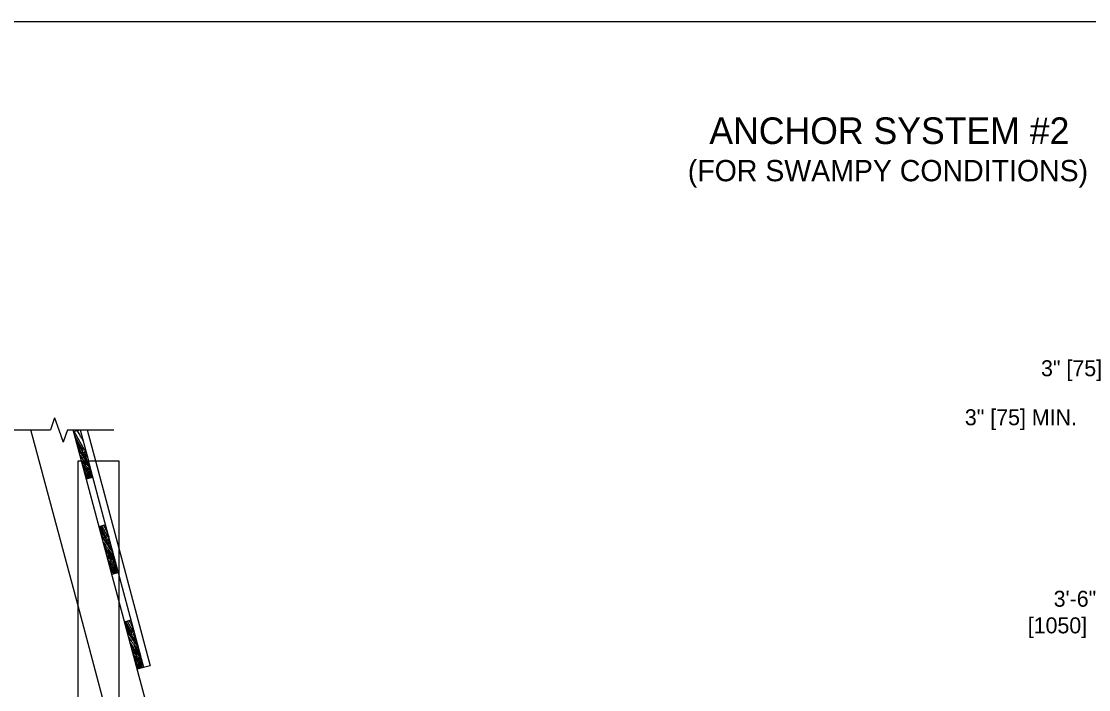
# Model space of a CAD drawing. Extents: x 49991.4 to 50021, y 49987.6 to 50011.4.
# Drawn here: x 50004.704 to 50008.713, y 49996.488 to 49998.999 of the extents above; entities that cross this region are included whole.
import ezdxf

# ---------------------------------------------------------------- set-up
doc = ezdxf.new("R2010")
doc.units = 0
for name, color, linetype in [('Level 1', 7, 'Continuous'), ('Level 2', 7, 'Continuous'), ('Level 4', 7, 'Continuous'), ('Level 6', 7, 'Continuous')]:
    doc.layers.add(name, color=color, linetype=linetype)

msp = doc.modelspace()

# ---------------------------------------------------------------- linework, layer by layer
at = {"layer": 'Level 1'}
for p, q in [((50004.9173, 49996.803), (50004.7403, 49997.464)), ((50004.9297, 49997.3481), (50004.8986, 49997.464)), ((50004.9003, 49997.4575), (50004.9249, 49997.464)), ((50004.9249, 49997.464), (50004.956, 49997.3481)), ((50004.9512, 49997.464), (50004.9825, 49997.3481)), ((50004.9173, 49995.084), (50004.9173, 49997.3481)), ((50004.9173, 49997.3481), (50004.9829, 49997.3481)), ((50004.9835, 49997.3481), (50005.0703, 49997.3481)), ((50005.0703, 49997.3481), (50005.0703, 49995.084)), ((50005.0703, 49997.0202), (50005.1888, 49996.578)), ((50005.1641, 49996.5715), (50005.0703, 49996.9218)), ((50005.2281, 49996.2339), (50005.0703, 49996.8231)), ((50005.0917, 49996.7435), (50005.1163, 49996.75)), ((50005.1887, 49996.578), (50005.1394, 49996.565))]:
    msp.add_line(p, q, dxfattribs=at)
msp.add_lwpolyline([(49999.3835, 49998.9992), (50016.7501, 49998.9992), (50016.7501, 49987.7988), (49999.3835, 49987.7988)], close=True, dxfattribs=at)
for points in [[(50004.9455, 49997.3874), (50004.9418, 49997.389), (50004.9031, 49997.4582)], [(50004.907, 49997.4327), (50004.9336, 49997.3899), (50004.9344, 49997.3884), (50004.9357, 49997.3871), (50004.9371, 49997.3841), (50004.9346, 49997.3906), (50004.933, 49997.3921), (50004.904, 49997.4439)], [(50004.9141, 49997.4611), (50004.921, 49997.4483), (50004.9236, 49997.4459), (50004.9245, 49997.4414), (50004.9271, 49997.4394), (50004.9275, 49997.4372), (50004.9283, 49997.4354), (50004.9306, 49997.4344), (50004.9362, 49997.422)], [(50004.9108, 49997.4184), (50004.9287, 49997.3903), (50004.9322, 49997.3858), (50004.9326, 49997.3821), (50004.9355, 49997.3791), (50004.9363, 49997.3743), (50004.9389, 49997.3703), (50004.941, 49997.3674), (50004.9444, 49997.3606), (50004.9482, 49997.3573), (50004.9508, 49997.3481)], [(50004.9143, 49997.4053), (50004.9236, 49997.3882), (50004.9262, 49997.3858), (50004.9271, 49997.3813), (50004.9297, 49997.3793), (50004.9301, 49997.3771), (50004.9309, 49997.3753), (50004.9332, 49997.3743), (50004.9352, 49997.3698), (50004.941, 49997.3629), (50004.9422, 49997.3595), (50004.9468, 49997.3537), (50004.9488, 49997.3481)], [(50004.9183, 49997.3905), (50004.9244, 49997.3826), (50004.9264, 49997.3785), (50004.9289, 49997.3736), (50004.9336, 49997.3685), (50004.9389, 49997.3593), (50004.9426, 49997.3544), (50004.9457, 49997.3481)], [(50004.9241, 49997.3691), (50004.9264, 49997.3679), (50004.9273, 49997.3673), (50004.9276, 49997.3657), (50004.929, 49997.3638), (50004.9308, 49997.3613), (50004.9342, 49997.3549)], [(50004.9257, 49997.3629), (50004.9284, 49997.3623), (50004.9313, 49997.3578), (50004.9349, 49997.3535), (50004.9352, 49997.3522), (50004.9365, 49997.3515)], [(50004.9531, 49997.3589), (50004.9512, 49997.3614), (50004.9482, 49997.3642), (50004.9474, 49997.3685), (50004.9434, 49997.3759), (50004.9402, 49997.3802)], [(50004.9461, 49997.3799), (50004.9451, 49997.3814), (50004.9421, 49997.385), (50004.9434, 49997.3819), (50004.9457, 49997.3799)], [(50004.9435, 49997.3757), (50004.948, 49997.3709), (50004.9509, 49997.3671)], [(50004.9395, 49997.3481), (50004.938, 49997.35), (50004.9388, 49997.3481)], [(50005.0937, 49996.7357), (50005.1118, 49996.7069), (50005.1153, 49996.7024), (50005.1157, 49996.6988), (50005.1186, 49996.6957), (50005.1194, 49996.6909), (50005.1219, 49996.6869), (50005.1241, 49996.6841), (50005.1275, 49996.6772), (50005.1313, 49996.6739), (50005.1354, 49996.6655), (50005.1371, 49996.664), (50005.1389, 49996.6591), (50005.1412, 49996.657)], [(50005.0951, 49996.7444), (50005.1167, 49996.7065), (50005.1174, 49996.705), (50005.1188, 49996.7037), (50005.1201, 49996.7007), (50005.1177, 49996.7072), (50005.1161, 49996.7087), (50005.0944, 49996.7442)], [(50005.0974, 49996.7221), (50005.1067, 49996.7048), (50005.1093, 49996.7024), (50005.1102, 49996.6979), (50005.1128, 49996.6959), (50005.1132, 49996.6937), (50005.1139, 49996.6919), (50005.1162, 49996.6909), (50005.1183, 49996.6864), (50005.1241, 49996.6795), (50005.1252, 49996.6761), (50005.1299, 49996.6703), (50005.1325, 49996.6647), (50005.1354, 49996.663), (50005.1362, 49996.6597), (50005.1394, 49996.655), (50005.143, 49996.6502)], [(50005.1286, 49996.7039), (50005.1249, 49996.7056), (50005.1022, 49996.7463)], [(50005.1084, 49996.7479), (50005.112, 49996.7413), (50005.1146, 49996.7389), (50005.1155, 49996.7344), (50005.1181, 49996.7324), (50005.1185, 49996.7302), (50005.1285, 49996.7046)], [(50005.1014, 49996.7071), (50005.1075, 49996.6992), (50005.1094, 49996.6951), (50005.112, 49996.6902), (50005.1167, 49996.6852), (50005.1219, 49996.6759), (50005.1257, 49996.671), (50005.1303, 49996.6616), (50005.1329, 49996.661), (50005.1395, 49996.6517), (50005.1424, 49996.6439), (50005.1445, 49996.6444)], [(50005.1071, 49996.6857), (50005.1095, 49996.6845), (50005.1104, 49996.6839), (50005.1106, 49996.6823), (50005.1121, 49996.6804), (50005.1139, 49996.6779), (50005.1173, 49996.6716)], [(50005.1088, 49996.6795), (50005.1115, 49996.6789), (50005.1144, 49996.6744), (50005.118, 49996.6701), (50005.1183, 49996.6688), (50005.1196, 49996.6682)], [(50005.1362, 49996.6755), (50005.1343, 49996.678), (50005.1313, 49996.6808), (50005.1305, 49996.6852), (50005.1264, 49996.6925), (50005.1233, 49996.6968)], [(50005.1292, 49996.6965), (50005.1281, 49996.698), (50005.1252, 49996.7016), (50005.1264, 49996.6985), (50005.1287, 49996.6965)], [(50005.1252, 49996.6937), (50005.1311, 49996.6875), (50005.1341, 49996.6836)], [(50005.1296, 49996.6389), (50005.1241, 49996.6487), (50005.1199, 49996.6569), (50005.1161, 49996.6625), (50005.1119, 49996.6676)], [(50005.1134, 49996.6619), (50005.1181, 49996.6535), (50005.1223, 49996.6483), (50005.118, 49996.6558), (50005.1131, 49996.6633)], [(50005.1159, 49996.6528), (50005.1228, 49996.6455), (50005.1268, 49996.6389)], [(50005.1615, 49996.5816), (50005.1535, 49996.5962), (50005.1515, 49996.5983), (50005.1479, 49996.6009), (50005.1447, 49996.6074), (50005.1378, 49996.6134), (50005.1346, 49996.6207), (50005.1279, 49996.6307), (50005.1246, 49996.6321), (50005.1226, 49996.6356), (50005.1191, 49996.6409)], [(50005.1251, 49996.6615), (50005.1241, 49996.6631), (50005.1211, 49996.6666), (50005.1224, 49996.6637), (50005.1246, 49996.6615)], [(50005.1358, 49996.6389), (50005.1315, 49996.6469), (50005.1289, 49996.6513), (50005.1276, 49996.6563), (50005.1264, 49996.6584), (50005.1293, 49996.6541), (50005.1342, 49996.6483), (50005.1379, 49996.6422), (50005.1399, 49996.6389)], [(50005.156, 49996.6019), (50005.1506, 49996.6071), (50005.1474, 49996.6138), (50005.1383, 49996.6218), (50005.1265, 49996.6388)], [(50005.1292, 49996.6388), (50005.1354, 49996.6307), (50005.1396, 49996.6238), (50005.1428, 49996.6224), (50005.1439, 49996.6207)], [(50005.1375, 49996.6389), (50005.1326, 49996.6482), (50005.1301, 49996.6512), (50005.1297, 49996.6518)], [(50005.1522, 49996.6161), (50005.1432, 49996.6274), (50005.1375, 49996.6325), (50005.1375, 49996.6363), (50005.1355, 49996.6388)], [(50005.1372, 49996.6388), (50005.1402, 49996.6349), (50005.1402, 49996.6336), (50005.1416, 49996.6311), (50005.1432, 49996.6307), (50005.1465, 49996.6259), (50005.1502, 49996.6205)], [(50005.1395, 49996.6388), (50005.1426, 49996.6332), (50005.1451, 49996.6308), (50005.1502, 49996.6233)], [(50005.155, 49996.5691), (50005.1506, 49996.5758), (50005.1468, 49996.5821), (50005.1445, 49996.5882), (50005.1439, 49996.5873), (50005.1416, 49996.5938), (50005.1387, 49996.5962), (50005.1371, 49996.6007), (50005.134, 49996.6046), (50005.131, 49996.6074), (50005.1303, 49996.6116), (50005.1239, 49996.6231)], [(50005.1245, 49996.6208), (50005.1309, 49996.614), (50005.134, 49996.6099), (50005.1375, 49996.6059), (50005.1414, 49996.6), (50005.147, 49996.5963), (50005.1507, 49996.5905), (50005.1551, 49996.5851), (50005.1632, 49996.5749)], [(50005.1289, 49996.6229), (50005.1279, 49996.6245), (50005.1249, 49996.628), (50005.1262, 49996.6251), (50005.1285, 49996.6229)], [(50005.1286, 49996.6054), (50005.1351, 49996.5921), (50005.1369, 49996.5905), (50005.1387, 49996.5856), (50005.1439, 49996.5809), (50005.1473, 49996.5726), (50005.1504, 49996.5705), (50005.1519, 49996.5683)], [(50005.1325, 49996.5911), (50005.1351, 49996.5894), (50005.136, 49996.5862), (50005.139, 49996.5815), (50005.1428, 49996.5767), (50005.1426, 49996.575), (50005.1441, 49996.5729), (50005.1484, 49996.5673)], [(50005.1338, 49996.5858), (50005.1393, 49996.5782), (50005.1422, 49996.5705), (50005.1441, 49996.5709), (50005.1473, 49996.5671)], [(50005.1574, 49996.5718), (50005.1539, 49996.5767), (50005.1502, 49996.5827), (50005.148, 49996.5858), (50005.147, 49996.5882), (50005.1451, 49996.5927), (50005.1476, 49996.5883), (50005.1502, 49996.5862), (50005.1527, 49996.5841), (50005.1547, 49996.5802), (50005.1562, 49996.5754), (50005.1606, 49996.5706)], [(50005.1525, 49996.581), (50005.1513, 49996.5834), (50005.1504, 49996.5845)]]:
    msp.add_lwpolyline(points, dxfattribs=at)
at = {"layer": 'Level 4'}
for p, q in [((50005.0703, 49996.8231), (50004.9297, 49997.3481)), ((50005.0177, 49997.118), (50004.956, 49997.3481)), ((50004.9825, 49997.3481), (50005.0703, 49997.0201)), ((50004.9728, 49997.2855), (50004.9483, 49997.2788)), ((50005.0703, 49996.9218), (50005.0177, 49997.118)), ((50005.0206, 49997.107), (50004.996, 49997.1003)), ((50005.0439, 49996.9218), (50005.0685, 49996.9285)), ((50005.0703, 49996.2315), (50004.9173, 49996.803))]:
    msp.add_line(p, q, dxfattribs=at)
for points in [[(50004.9199, 49997.3843), (50004.92, 49997.3843)], [(50004.928, 49997.3545), (50004.9279, 49997.3546)], [(50004.9701, 49997.2957), (50004.9621, 49997.3102), (50004.9601, 49997.3123), (50004.9565, 49997.3149), (50004.9533, 49997.3214), (50004.9464, 49997.3274), (50004.9432, 49997.3347), (50004.9365, 49997.3447), (50004.9332, 49997.3461), (50004.9298, 49997.3476)], [(50004.9637, 49997.283), (50004.9592, 49997.2898), (50004.9554, 49997.2961), (50004.9531, 49997.3022), (50004.9525, 49997.3013), (50004.9502, 49997.3078), (50004.9473, 49997.3102), (50004.9457, 49997.3147), (50004.9426, 49997.3186), (50004.9396, 49997.3214), (50004.9389, 49997.3256), (50004.9327, 49997.3368)], [(50004.9375, 49997.3369), (50004.9365, 49997.3385), (50004.9335, 49997.342), (50004.9348, 49997.3391), (50004.9371, 49997.3369)], [(50004.9348, 49997.333), (50004.9395, 49997.328), (50004.9426, 49997.3239), (50004.9461, 49997.3199), (50004.95, 49997.314), (50004.9556, 49997.3103), (50004.9593, 49997.3045), (50004.9637, 49997.2991), (50004.9719, 49997.2888)], [(50004.9375, 49997.3189), (50004.9437, 49997.3061), (50004.9455, 49997.3045), (50004.9473, 49997.2996), (50004.9525, 49997.2949), (50004.9559, 49997.2866), (50004.959, 49997.2845), (50004.9606, 49997.2822)], [(50004.9647, 49997.3159), (50004.9592, 49997.3211), (50004.956, 49997.3278), (50004.9469, 49997.3358), (50004.9386, 49997.3481)], [(50004.9395, 49997.3481), (50004.944, 49997.3447), (50004.9482, 49997.3378), (50004.9514, 49997.3364), (50004.9525, 49997.3347)], [(50004.9608, 49997.3301), (50004.9518, 49997.3414), (50004.9461, 49997.3465), (50004.9457, 49997.3481)], [(50004.9488, 49997.3481), (50004.9488, 49997.3476), (50004.9502, 49997.3451), (50004.9518, 49997.3447), (50004.9551, 49997.3399), (50004.96, 49997.3331)], [(50004.9508, 49997.3481), (50004.9512, 49997.3472), (50004.9537, 49997.3448), (50004.9589, 49997.3372)], [(50004.9412, 49997.3051), (50004.9437, 49997.3034), (50004.9446, 49997.3002), (50004.9476, 49997.2955), (50004.9514, 49997.2907), (50004.9512, 49997.289), (50004.9527, 49997.2869), (50004.9571, 49997.2812)], [(50004.9427, 49997.2995), (50004.9479, 49997.2922), (50004.9508, 49997.2845), (50004.9527, 49997.2849), (50004.9561, 49997.2809)], [(50004.9668, 49997.2839), (50004.9625, 49997.2907), (50004.9588, 49997.2967), (50004.9566, 49997.2998), (50004.9556, 49997.3022), (50004.9537, 49997.3067), (50004.9562, 49997.3023), (50004.9588, 49997.3002), (50004.9613, 49997.2981), (50004.9633, 49997.2942), (50004.9648, 49997.2894), (50004.9693, 49997.2845)], [(50004.9611, 49997.295), (50004.9599, 49997.2974), (50004.959, 49997.2985)], [(50004.9982, 49997.0924), (50005.0161, 49997.0639), (50005.0196, 49997.0594), (50005.02, 49997.0558), (50005.0229, 49997.0527), (50005.0237, 49997.0479), (50005.0262, 49997.0439), (50005.0284, 49997.0411), (50005.0318, 49997.0342), (50005.0356, 49997.0309), (50005.0397, 49997.0225), (50005.0414, 49997.021), (50005.0432, 49997.0161), (50005.0456, 49997.014)], [(50004.9995, 49997.1013), (50005.021, 49997.0635), (50005.0217, 49997.062), (50005.0231, 49997.0607), (50005.0244, 49997.0577), (50005.022, 49997.0642), (50005.0204, 49997.0657), (50005.0014, 49997.1018)], [(50005.0019, 49997.0789), (50005.011, 49997.0618), (50005.0136, 49997.0594), (50005.0145, 49997.0549), (50005.0171, 49997.0529), (50005.0175, 49997.0507), (50005.0182, 49997.0489), (50005.0205, 49997.0479), (50005.0226, 49997.0434), (50005.0284, 49997.0365), (50005.0295, 49997.0331), (50005.0342, 49997.0273), (50005.0368, 49997.0217), (50005.0397, 49997.02), (50005.0405, 49997.0167), (50005.0437, 49997.012), (50005.0474, 49997.0072)], [(50005.033, 49997.0609), (50005.0292, 49997.0626), (50005.0066, 49997.1032)], [(50005.0128, 49997.1049), (50005.0163, 49997.0983), (50005.0189, 49997.0959), (50005.0198, 49997.0914), (50005.0224, 49997.0894), (50005.0228, 49997.0872), (50005.0328, 49997.0617)], [(50005.0059, 49997.064), (50005.0118, 49997.0562), (50005.0137, 49997.0521), (50005.0163, 49997.0472), (50005.021, 49997.0422), (50005.0262, 49997.0329), (50005.03, 49997.028), (50005.0346, 49997.0186), (50005.0372, 49997.018), (50005.0438, 49997.0087), (50005.0467, 49997.0009), (50005.0491, 49997.001)], [(50005.0116, 49997.0427), (50005.0138, 49997.0415), (50005.0147, 49997.0409), (50005.0149, 49997.0393), (50005.0164, 49997.0374), (50005.0182, 49997.0349), (50005.0216, 49997.0286)], [(50005.0132, 49997.0365), (50005.0158, 49997.0359), (50005.0187, 49997.0314), (50005.0223, 49997.0271), (50005.0226, 49997.0258), (50005.0239, 49997.0252)], [(50005.0407, 49997.0324), (50005.0386, 49997.035), (50005.0356, 49997.0378), (50005.0348, 49997.0422), (50005.0307, 49997.0495), (50005.0276, 49997.0538)], [(50005.0335, 49997.0535), (50005.0324, 49997.055), (50005.0295, 49997.0586), (50005.0307, 49997.0555), (50005.033, 49997.0535)], [(50005.0308, 49997.0494), (50005.0354, 49997.0445), (50005.0385, 49997.0406)], [(50005.0157, 49997.0274), (50005.0397, 49996.9877), (50005.0439, 49996.9808), (50005.0471, 49996.9794), (50005.0482, 49996.9777)], [(50005.0181, 49997.0183), (50005.0224, 49997.0105), (50005.0266, 49997.0053), (50005.0223, 49997.0128), (50005.0176, 49997.02)], [(50005.0204, 49997.0096), (50005.0271, 49997.0025), (50005.0311, 49996.9959)], [(50005.0658, 49996.9388), (50005.0578, 49996.9532), (50005.0558, 49996.9553), (50005.0522, 49996.9579), (50005.049, 49996.9644), (50005.0421, 49996.9704), (50005.0389, 49996.9777), (50005.0322, 49996.9877), (50005.0289, 49996.9891), (50005.0269, 49996.9926), (50005.0236, 49996.9977)], [(50005.0294, 49997.0185), (50005.0284, 49997.0201), (50005.0254, 49997.0236), (50005.0267, 49997.0207), (50005.0289, 49997.0185)], [(50005.0401, 49996.9959), (50005.0358, 49997.0039), (50005.0332, 49997.0083), (50005.0319, 49997.0133), (50005.0307, 49997.0154), (50005.0336, 49997.0111), (50005.0385, 49997.0053), (50005.0422, 49996.9992), (50005.0442, 49996.9959)], [(50005.0604, 49996.9589), (50005.0549, 49996.9641), (50005.0517, 49996.9708), (50005.0426, 49996.9788), (50005.0311, 49996.9959)], [(50005.0418, 49996.9959), (50005.0369, 49997.0052), (50005.0344, 49997.0082), (50005.034, 49997.0088)], [(50005.0565, 49996.9731), (50005.0475, 49996.9844), (50005.0418, 49996.9895), (50005.0418, 49996.9933), (50005.0401, 49996.9959)], [(50005.0418, 49996.9959), (50005.0445, 49996.9919), (50005.0445, 49996.9906), (50005.0459, 49996.9881), (50005.0475, 49996.9877), (50005.0508, 49996.9829), (50005.0557, 49996.9762)], [(50005.0442, 49996.9959), (50005.0469, 49996.9902), (50005.0494, 49996.9878), (50005.0546, 49996.9802)], [(50005.0594, 49996.926), (50005.0549, 49996.9328), (50005.0511, 49996.9391), (50005.0488, 49996.9452), (50005.0482, 49996.9443), (50005.0459, 49996.9508), (50005.043, 49996.9532), (50005.0414, 49996.9577), (50005.0383, 49996.9616), (50005.0353, 49996.9644), (50005.0346, 49996.9686), (50005.0284, 49996.9799)], [(50005.0332, 49996.9799), (50005.0322, 49996.9815), (50005.0292, 49996.985), (50005.0305, 49996.9821), (50005.0328, 49996.9799)], [(50005.0305, 49996.976), (50005.0352, 49996.971), (50005.0383, 49996.9669), (50005.0418, 49996.9629), (50005.0457, 49996.957), (50005.0513, 49996.9533), (50005.055, 49996.9475), (50005.0594, 49996.9421), (50005.0676, 49996.9318)], [(50005.0332, 49996.9619), (50005.0394, 49996.9491), (50005.0412, 49996.9475), (50005.043, 49996.9426), (50005.0482, 49996.9379), (50005.0516, 49996.9296), (50005.0547, 49996.9275), (50005.0563, 49996.9252)], [(50005.0369, 49996.9481), (50005.0394, 49996.9464), (50005.0403, 49996.9432), (50005.0433, 49996.9385), (50005.0471, 49996.9337), (50005.0469, 49996.932), (50005.0484, 49996.9299), (50005.0528, 49996.9242)], [(50005.0384, 49996.9426), (50005.0436, 49996.9352), (50005.0465, 49996.9275), (50005.0484, 49996.9279), (50005.0518, 49996.924)], [(50005.0625, 49996.9269), (50005.0582, 49996.9337), (50005.0545, 49996.9397), (50005.0523, 49996.9428), (50005.0513, 49996.9452), (50005.0494, 49996.9497), (50005.0519, 49996.9453), (50005.0545, 49996.9432), (50005.057, 49996.9411), (50005.059, 49996.9372), (50005.0605, 49996.9324), (50005.065, 49996.9276)], [(50005.0568, 49996.938), (50005.0556, 49996.9404), (50005.0547, 49996.9415)]]:
    msp.add_lwpolyline(points, dxfattribs=at)
at = {"layer": 'Level 6'}
for p, q in [((50004.8295, 49997.5097), (50004.8133, 49997.464)), ((50004.8295, 49997.5097), (50004.8457, 49997.464)), ((50004.6041, 49997.464), (50004.8133, 49997.464)), ((50004.8457, 49997.464), (50004.8619, 49997.4183)), ((50004.8781, 49997.464), (50004.8619, 49997.4183)), ((50004.8781, 49997.464), (50005.0512, 49997.464))]:
    msp.add_line(p, q, dxfattribs=at)

# ---------------------------------------------------------------- texts
at = {"layer": 'Level 2'}
for s, height, p in [('ANCHOR SYSTEM #2', 0.1, (50007.2885, 49998.5383)), ('(FOR SWAMPY CONDITIONS)', 0.08, (50007.2076, 49998.3983)), ('3" [75]', 0.06, (50008.5345, 49997.6657)), ('3" [75] MIN.', 0.06, (50008.2484, 49997.4816)), ('3\'-6"', 0.06, (50008.5819, 49996.7997)), ('[1050]', 0.06, (50008.4845, 49996.6997))]:
    msp.add_text(s, height=height, dxfattribs=at).set_placement(p)

doc.saveas('drawing.dxf')
